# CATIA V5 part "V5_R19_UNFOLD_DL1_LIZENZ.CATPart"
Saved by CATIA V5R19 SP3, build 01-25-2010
Part number: UNFOLD
Nomenclature: UNFOLD
Bounding box of the stored display mesh (mm): x 0 to 2570.695, y 0 to 718.013, z 0 to 493.429
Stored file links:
  C:\___TMP\V5_R19_UNFOLD_DL1_LIZENZ.CATPart
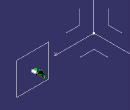
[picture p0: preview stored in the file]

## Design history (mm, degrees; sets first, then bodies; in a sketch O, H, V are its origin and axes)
AxisSystem1: origin (0, 0, 0), X (1, 0, 0), Y (0, 1, 0), Z (0, 0, 1)
Set1 "UNFOLD"
  DatumSurface1 "DUMMY"
  Unfold1 "Unfold.doppelklick und  DUMMY austauschen": SpecsToUnfold DatumSurface1, Origin vertex [face of DatumSurface1], ReferenceDirection edge of DatumSurface1, AxisFirstDirection (0, 0, 1)
Set2 "UNFOLD_2"
  Point1 "Positionspunkt": (0, 0, 220)
  Plane1 "Plane XY": type OffsetPt, RefPlane xy-plane, RefPoint Point1
  Plane2 "Plane YZ": type OffsetPt, RefPlane yz-plane, RefPoint Point1
  Plane3 "Plane ZX": type OffsetPt, RefPlane zx-plane, RefPoint Point1
  Sketch1 "... kurve XY" on Plane1, origin (0, 0, 220), H (1, 0, 0), V (0, 1, 0)
    point P1 (0, 0)
    coincidence: P1 O
  Sketch2 "... kurve YZ" on Plane2, origin (0, 0, 220), H (0, 1, 0), V (0, 0, 1)
    point P1 (0, 0)
    coincidence: P1 O
  Sketch3 "... kurve ZX" on Plane3, origin (0, 0, 220), H (1, 0, 0), V (0, 0, 1)
    point P1 (0, 0)
    coincidence: O P1
  DatumSurface2 "DUMMY_2"
  Plane4 "Plane   TARGET_PLANE": type Offset, RefPlane ZX plane of AxisSystem1, Offset 387
  Point2 "Point   TARGET_ORIGIN": type OnPlane, Support {inverselocal InverseElem Plane4}, RefPoint Point1, H 2451.59, V 79.339, Direction (1, 0, 0)
  Project1 "Project   REFERENCE_ORIGIN": ToProject Point2, Support DatumSurface2, Direction Plane4
  Line1 "Line   REFERENCE_DIRECTION": type PtDir, RefPoint Project1, Direction Plane2, Start 0, End 20
  Unfold2 "Unfold": SpecsToUnfold DatumSurface2, Origin Project1, ReferenceDirection Line1, AxisPlane {inverselocal InverseElem Plane4}, AxisOrigin Point2, AxisFirstDirection (0, 0, 1)
Body1 (main body)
